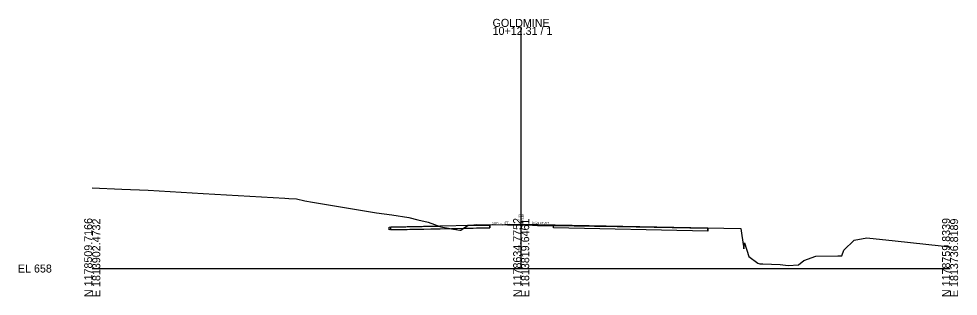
# Model space of a CAD drawing. Extents: x -26 to 1603, y -10 to 1590.
# Drawn here: x -25.7 to 302.8, y -9.7 to 87.4 of the extents above; entities that cross this region are included whole.
import ezdxf

# ---------------------------------------------------------------- set-up
doc = ezdxf.new("R2010")
doc.units = 0
for name, color, linetype in [('Default', 7, 'Continuous'), ('RD_GPK_XS_Cell', 7, 'Continuous'), ('RD_XS_Base', 7, 'Continuous'), ('RD_XS_ExGround', 7, 'Continuous'), ('RD_XS_Misc_Line', 7, 'Continuous'), ('RD_XS_Pave', 7, 'Continuous'), ('RD_XS_TX_Elev_EX', 7, 'Continuous'), ('RD_XS_TX_Slope', 7, 'Continuous')]:
    doc.layers.add(name, color=color, linetype=linetype)

msp = doc.modelspace()

# ---------------------------------------------------------------- linework, layer by layer
at = {"layer": 'Default'}
for p, q in [((150, 15.46), (104.41, 14.51)), ((215.3, 14.1), (150, 15.46))]:
    msp.add_line(p, q, dxfattribs=at)
at = {"layer": 'RD_GPK_XS_Cell'}
for p, q in [((150, 0), (150, 84.58)), ((0, 0), (150, 0)), ((150, 0), (300, 0))]:
    msp.add_line(p, q, dxfattribs=at)
at = {"layer": 'RD_XS_Base'}
for p, q in [((104.41, 13.51), (139.09, 14.23)), ((139.09, 14.23), (139.09, 15.23)), ((161.32, 14.22), (161.32, 15.03)), ((215.3, 13.1), (161.32, 14.22))]:
    msp.add_line(p, q, dxfattribs=at)
at = {"layer": 'RD_XS_ExGround'}
msp.add_lwpolyline([(0, 28.19), (10.34, 27.76), (19.5, 27.38), (38.75, 26.29), (67.32, 24.66), (68.73, 24.57), (71.41, 24.43), (74.29, 23.71), (77.02, 23.25), (99.35, 19.55), (104.8, 18.82), (110.71, 17.87), (113.83, 17.02), (117.46, 16.25), (121.96, 14.59), (128.52, 13.47), (128.85, 13.41), (131.32, 15.1), (132.56, 15.19), (134.25, 15.4), (145.27, 15.31), (150, 15.28), (150.78, 15.28), (151.26, 15.25), (152.14, 15.24), (155.73, 15.06), (161.39, 15.03), (175.62, 14.82), (176.79, 14.8), (201, 14.48), (202.45, 14.46), (203.12, 14.45), (226.79, 14.06), (227.09, 12.4), (227.86, 6.93), (228.08, 8.99), (229.62, 4.25), (232.82, 1.89), (233.45, 1.69), (234.47, 1.6), (240.59, 1.39), (243.42, 1.02), (247.03, 1.27), (248.83, 2.8), (253.08, 4.29), (260.79, 4.49), (261.66, 4.49), (262.18, 4.48), (262.89, 6.47), (266.42, 9.94), (270.9, 10.74), (280.84, 9.67), (296.93, 7.97), (298.88, 7.66), (299.83, 7.49), (300, 7.52)], dxfattribs=at)
at = {"layer": 'RD_XS_Misc_Line'}
for points in [[(121.22, 14.86), (121.96, 14.59), (125.68, 13.95), (103.81, 13.5), (103.81, 14.5)], [(125.68, 13.95), (128.52, 13.47), (128.85, 13.41), (129.77, 14.04)], [(129.77, 14.04), (131.28, 15.07), (139.09, 15.23), (139.09, 14.23)], [(143.39, 15.32), (139.09, 15.23), (131.28, 15.07), (131.32, 15.1), (132.56, 15.19), (134.25, 15.4)], [(176.79, 14.8), (190.25, 14.62), (215.3, 14.1), (215.3, 13.1), (161.32, 14.22), (161.32, 15.03), (161.39, 15.03), (175.62, 14.82)]]:
    msp.add_lwpolyline(points, close=True, dxfattribs=at)
at = {"layer": 'RD_XS_Pave'}
for p, q in [((104.41, 13.51), (104.41, 14.51)), ((215.3, 13.1), (215.3, 14.1))]:
    msp.add_line(p, q, dxfattribs=at)

# ---------------------------------------------------------------- texts
at = {"layer": 'Default'}
msp.add_text(' 673.46', height=0.8, rotation=90, dxfattribs=at).set_placement((150.91, 15.46))
at = {"layer": 'RD_GPK_XS_Cell'}
for s, p in [('GOLDMINE', (140, 84.58)), ('10+12.31 / 1', (140, 81.78)), ('EL 658', (-26, -1.4))]:
    msp.add_text(s, height=2.8, dxfattribs=at).set_placement(p)
for s, p in [('N 1178509.7166', (0, -10)), ('E 1813902.4732', (2.8, -10)), ('N 1178634.7752', (150, -10)), ('E 1813819.6461', (152.8, -10)), ('N 1178759.8339', (300, -10)), ('E 1813736.8189', (302.8, -10))]:
    msp.add_text(s, height=2.8, rotation=90, dxfattribs=at).set_placement(p)
at = {"layer": 'RD_XS_TX_Elev_EX'}
msp.add_text('673.28', height=0.8, rotation=90, dxfattribs=at).set_placement((149.95, 15.62))
at = {"layer": 'RD_XS_TX_Slope'}
for rotation, p in [(1.1916, (139.71, 15.5)), (358.8084, (153.72, 15.63))]:
    msp.add_text('0.021 FT./FT.', height=0.75, rotation=rotation, dxfattribs=at).set_placement(p)

doc.saveas('drawing.dxf')
